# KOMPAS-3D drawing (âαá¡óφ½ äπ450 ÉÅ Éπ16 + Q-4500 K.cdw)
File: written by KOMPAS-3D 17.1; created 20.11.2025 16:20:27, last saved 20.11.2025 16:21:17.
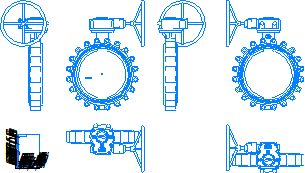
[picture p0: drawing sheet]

Sheet 1: A4, portrait

Title block, sheet 1: name: Гранвэл Ду450; material: Сталь 10  ГОСТ 1050-88; mass: 129,84; sheets: 1; sheet format: A4

Views: Проекционный вид 3, Проекционный вид 4
Referenced files in \\adlc.lan\data\АДЛ_ПКД\3D-модели\ADL production\Дисковые поворотные затворы ГРАНВЭЛ\с резьбовыми проушинами с китайским редуктором Ру 16\KOMPAS 3D\: Гранвэл Ду450 РП Ру16 + Q-4500 K.m3d
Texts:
  Andrey
  АДЛ
Dimensions and other numbers on the sheet: 1:1; 1; 129,84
